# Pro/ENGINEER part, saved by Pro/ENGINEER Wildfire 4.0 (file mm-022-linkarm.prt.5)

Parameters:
  METRIC = "NO"

Other parameters: PITCH, DRILL_DIAMETER, THREAD_DIAMETER, THREADS_PER_INCH, THREAD_DEPTH, THREAD_LENGTH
